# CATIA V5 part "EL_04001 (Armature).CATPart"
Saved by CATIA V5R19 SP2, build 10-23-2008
Part number: Armature
Bounding box of the stored display mesh (mm): x 0 to 331.074, y 0 to 115, z 0 to 2
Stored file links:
  C:\Users\loics\Documents\Centrale Lyon\EPSA\GIT\ELIZ-2021\EL_Electrical\CATIA\EL_A0100 (Dash Panel)\EL_04001 (Armature).CATPart
  C:\Users\loics\Documents\Centrale Lyon\EPSA\GIT\ELIZ-2021\EL_Electrical\CATIA\EL_A0100 (Dash Panel)\EL_04004 (Bistable Switch).CATPart
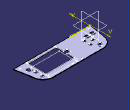
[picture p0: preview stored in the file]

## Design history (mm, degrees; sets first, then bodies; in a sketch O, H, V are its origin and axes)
Body1 (main body)
  Sketch1 on xy-plane, origin (0, 0, 0), H (1, 0, 0), V (0, 1, 0)
    line L1 (58.0371, 115) -> (273.0371, 115)
    line L2 (317.3534, 77.8142) -> (331.0742, 0)
    line L3 (331.0742, 0) -> (0, 0)
    point P2 (0, 0)
    line L4 (0, 0) -> (13.7207, 77.8142)
    arc A1 centre (58.0371, 70) radius 45 from (13.7207, 77.8142) to (58.0371, 115) cw
    point P4 (58.0371, 115)
    arc A2 centre (273.0371, 70) radius 45 from (273.0371, 115) to (317.3534, 77.8142) cw
    point P6 (273.0371, 115)
    distance H L3 = 0
    angle L4 L3 = 80
    angle L3 L2 = 80
    radius A1 = 45
    radius A2 = 45
    distance P4 P6 = 215
    distance L3 L1 = 115
    distance V P2 = 0
    horizontal: L1 H, L3 H
    tangency: A1 L4, A1 L1, A2 L1, A2 L2
  Pad1: profile Sketch1, direction (0, 0, 1), length 2
  Sketch2 on end face of Pad1, origin (0, 0, 2), H (1, 0, 0), V (0, 1, 0)
    construction line L1 (157.2489, 99) -> (157.2489, 5)
    construction line L2 (277.2489, 99) -> (277.2489, 5)
    circle A1 centre (157.2489, 99) radius 1.6
    circle A2 centre (157.2489, 5) radius 1.6
    circle A3 centre (277.2489, 5) radius 1.6
    circle A4 centre (277.2489, 99) radius 1.6
    construction line L3 (157.2489, 99) -> (277.2489, 99)
    construction line L4 (157.2489, 5) -> (277.2489, 5)
    circle A5 centre (300.8938, 36.6) radius 9.6
    point P5 (300.8938, 36.6)
    point P6 (163.611, 108)
    construction line L5 (142.011, 108) -> (182.011, 108)
    point P7 (142.011, 108)
    point P8 (182.011, 108)
    circle A6 centre (162.011, 108) radius 1.6
    point P9 (162.011, 108)
    circle A7 centre (182.011, 108) radius 2.5
    circle A8 centre (142.011, 108) radius 2.5
    reference projected line E2 (269.5105, 115) -> (54.5105, 115) from edge [face of Pad1 from Sketch1.L1 | end face of Pad1]
    point P10 (133.81, 30)
    point P11 (185.31, 30)
    arc A9 centre (293.2489, 60) radius 6.35 from (293.8989, 53.6834) to (292.5989, 53.6834) ccw
    point P12 (293.2489, 60)
    construction line L6 (324.021, 0) -> (324.021, 124.6381)
    point P13 (324.021, 0)
    construction line L7 (300.8938, 36.6) -> (355.7124, 46.266)
    point P16 (293.2489, 86.5)
    arc A10 centre (293.2489, 86.5) radius 6.35 from (293.8989, 80.1834) to (292.5989, 80.1834) ccw
    construction line L8 (24.6, 36.6) -> (49.6, 36.6)
    point P17 (24.6, 36.6)
    point P18 (49.6, 36.6)
    circle A11 centre (49.6, 36.6) radius 9.6
    circle A12 centre (24.6, 36.6) radius 9.6
    arc A13 centre (49.6, 61.6) radius 6.35 from (50.25, 55.2834) to (48.95, 55.2834) ccw
    point P19 (49.6, 61.6)
    arc A14 centre (72.1167, 74.6) radius 6.35 from (72.7667, 68.2834) to (71.4667, 68.2834) ccw
    point P20 (72.1167, 74.6)
    arc A15 centre (72.1167, 48.6) radius 6.35 from (72.7667, 42.2834) to (71.4667, 42.2834) ccw
    point P21 (72.1167, 48.6)
    point P22 (83.0841, 46.1824)
    point P23 (105.3433, 34.8012)
    point P24 (102.1, 31.6)
    circle A16 centre (37.1, 49.5518) radius 2.5
    construction line L9 (324.021, 75.8985) -> (330.0441, 41.74)
    point P26 (324.021, 75.8985)
    point P27 (330.0441, 41.74)
    reference projected line E3 (330.8615, 1.2061) -> (320.6673, 59.0203) from edge [face of Pad1 from Sketch1.L2 | end face of Pad1]
    arc A17 centre (51, 94.515) radius 8.1 from (50.15, 102.5703) to (51.85, 102.5703) ccw
    point P28 (51, 94.515)
    line L10 (292.5989, 81.5) -> (293.8989, 81.5)
    line L11 (293.8989, 81.5) -> (293.8989, 80.1834)
    line L12 (292.5989, 81.5) -> (292.5989, 80.1834)
    construction line L13 (37.1, 49.5518) -> (24.6, 36.6)
    point P33 (24.6, 36.6)
    construction line L14 (37.1, 49.5518) -> (49.6, 36.6)
    point P34 (49.6, 36.6)
    line L15 (292.5989, 53.6834) -> (292.5989, 55)
    line L16 (292.5989, 55) -> (293.8989, 55)
    line L17 (293.8989, 55) -> (293.8989, 53.6834)
    line L18 (50.15, 102.5703) -> (50.15, 101.615)
    line L19 (50.15, 101.615) -> (51.85, 101.615)
    line L20 (51.85, 101.615) -> (51.85, 102.5703)
    line L21 (48.95, 55.2834) -> (48.95, 56.6)
    line L22 (48.95, 56.6) -> (50.25, 56.6)
    line L23 (50.25, 56.6) -> (50.25, 55.2834)
    line L24 (71.4667, 68.2834) -> (71.4667, 69.6)
    line L25 (71.4667, 69.6) -> (72.7667, 69.6)
    line L26 (72.7667, 69.6) -> (72.7667, 68.2834)
    reference projected line E4 (269.5105, 115) -> (54.5105, 115) from edge [face of Pad1 from Sketch1.L1 | end face of Pad1]
    reference projected line E5 (269.5105, 115) -> (54.5105, 115) from edge [face of Pad1 from Sketch1.L1 | end face of Pad1]
    reference projected line E6 (269.5105, 115) -> (54.5105, 115) from edge [face of Pad1 from Sketch1.L1 | end face of Pad1]
    reference projected line E7 (0, 0) -> (331.0742, 0) from edge [face of Pad1 from Sketch1.L3 | end face of Pad1]
    line L27 (156.2489, 88.19) -> (278.2489, 88.19)
    line L28 (278.2489, 88.19) -> (278.2489, 10.492)
    line L29 (278.2489, 10.492) -> (156.2489, 10.492)
    construction line L30 (293.2489, 60) -> (293.2489, 86.5)
    reference projected line E8 (273.0371, 115) -> (58.0371, 115) from edge [face of Pad1 from Sketch1.L1 | end face of Pad1]
    circle A18 centre (313.7268, 12) radius 1.6
    point P57 (313.7268, 12)
    reference projected line E9 (0, 0) -> (331.0742, 0) from edge [face of Pad1 from Sketch1.L3 | end face of Pad1]
    reference projected line E10 (331.0742, 0) -> (317.3534, 77.8142) from edge [face of Pad1 from Sketch1.L2 | end face of Pad1]
    circle A19 centre (17.3473, 12) radius 1.6
    point P58 (17.3473, 12)
    reference projected line E11 (0, 0) -> (331.0742, 0) from edge [face of Pad1 from Sketch1.L3 | end face of Pad1]
    reference projected line E12 (13.7207, 77.8142) -> (0, 0) from edge [face of Pad1 from Sketch1.L4 | end face of Pad1]
    reference projected line E13 (331.0742, 0) -> (317.3534, 77.8142) from edge [face of Pad1 from Sketch1.L2 | end face of Pad1]
    line L31 (72.7667, 42.2834) -> (72.7667, 43.6)
    line L32 (71.4667, 43.6) -> (72.7667, 43.6)
    construction line L33 (72.1167, 74.6) -> (72.1167, 48.6)
    line L34 (71.4667, 43.6) -> (71.4667, 42.2834)
    axis line L35 (72.1167, 61.6) -> (49.6, 61.6)
    point P61 (72.1167, 61.6)
    line L36 (156.2489, 88.19) -> (156.2489, 57.0885)
    line L37 (156.2489, 57.0885) -> (141.2489, 57.0885)
    line L38 (141.2489, 57.0885) -> (141.2489, 41.6307)
    line L39 (141.2489, 41.6307) -> (156.2489, 41.6307)
    point P65 (156.2489, 41.6307)
    line L40 (156.2489, 41.6307) -> (156.2489, 10.492)
    reference projected line E14 (156.2489, 57.0885) -> (154.2489, 57.0885) from edge of DatumCurve1
    reference projected line E15 (156.2489, 41.6307) -> (154.2489, 41.6307) from edge of DatumCurve2
    radius A1 = 1.6
    radius A2 = 1.6
    radius A3 = 1.6
    radius A4 = 1.6
    length L2 = 94
    radius A5 = 9.6
    radius A8 = 2.5
    radius A7 = 2.5
    radius A6 = 1.6
    distance P7 P9 = 20
    distance P9 P8 = 20
    distance P9 V = 162.011
    distance L5 E2 = 7
    distance P10 V = 133.81
    radius A9 = 6.35
    distance L6 V = 324.021
    radius A10 = 6.35
    radius A12 = 9.6
    radius A11 = 9.6
    length L8 = 25
    distance P17 V = 24.6
    radius A13 = 6.35
    distance P19 P18 = 25
    distance P19 V = 49.6
    radius A14 = 6.35
    radius A15 = 6.35
    radius A16 = 2.5
    distance L9 A5 = 20
    radius A17 = 8.1
    distance P28 V = 51
    length L10 = 1.3
    distance P16 L12 = 0.65
    distance L10 P16 = 5
    distance P20 P19 = 26
    length L13 = 18
    length L14 = 18
    length L16 = 1.3
    distance L17 P12 = 0.65
    length L19 = 1.7
    distance L20 P28 = 0.85
    distance L19 P28 = 7.1
    length L22 = 1.3
    distance L21 P19 = 0.65
    length L25 = 1.3
    distance L26 P20 = 0.65
    distance L25 P20 = 5
    distance L22 P19 = 5
    distance P12 L16 = 5
    distance P28 E4 = 20.485
    distance P34 E5 = 78.4
    distance P5 E6 = 78.4
    length L3 = 120
    distance L4 E7 = 5
    distance L2 P16 = 16
    length L28 = 77.698
    length L27 = 122
    distance L4 L29 = 5.492
    distance L28 L2 = 1
    distance P5 L30 = 7.6449
    distance P16 E8 = 28.5
    length L30 = 26.5
    radius A18 = 1.6
    distance P57 E9 = 12
    distance P57 E10 = 15
    radius A19 = 1.6
    distance P58 E11 = 12
    distance E12 P58 = 15
    distance P12 E13 = 26.8317
    distance P21 L32 = 5
    length L32 = 1.3
    distance P21 L31 = 0.65
    length L33 = 26
    distance L35 P21 = 13
    length L37 = 15
    vertical: L1 V, L2 V, L6 V, L11 V, L12 V, L15 V, L17 V, L18 V, L20 V, L21 V, L23 V, L24 V, L26 V, L28 V, L30 V, L31 V, L33 V, L34 V, L36 V, L40 V, L38 V
    horizontal: L3 H, L4 H, L5 H, L8 H, L10 H, L16 H, L19 H, L22 H, L25 H, L27 H, L29 H, L32 H, L35 H, L37 H, L39 H
    coincidence: P9 L5, A6 P6, P13 H, P26 L6, P27 L7, L13 P17, L14 P18, P33 P17, P34 P18, P61 L33, P65 L36, L37 E14, L39 E15
    perpendicularity: L9 L7
    parallelism: L9 E3
  Pocket1: profile Sketch2, direction (0, 0, -1), length 2
  Sketch3 on start face of Pad1, origin (0, 0, 0), H (1, 0, 0), V (0, -1, 0)
    line L1 (162.4989, -29.4) -> (282.4989, -29.4)
    line L2 (282.4989, -29.4) -> (282.4989, -103.4)
    line L3 (282.4989, -103.4) -> (162.4989, -103.4)
    line L4 (162.4989, -103.4) -> (162.4989, -29.4)
    reference projected line E1 (175.7489, -32.8) -> (281.2489, -32.8) from edge of Sketch2
    reference projected line E2 (169.7489, -80) -> (169.7489, -12.8) from edge of Sketch2
    length L1 = 120
    distance E1 L1 = 3.4
    length L4 = 74
    distance L4 E2 = 7.25
    horizontal: L1 H, L3 H
    vertical: L2 V, L4 V
  Sketch4 on end face of Pad1, origin (0, 0, 2), H (1, 0, 0), V (0, 1, 0)
    line L1 (58.0371, 115) -> (273.0371, 115)
    line L2 (317.3534, 77.8142) -> (331.0742, 0)
    line L3 (331.0742, 0) -> (0, 0)
    point P2 (0, 0)
    line L4 (0, 0) -> (13.7207, 77.8142)
    arc A1 centre (58.0371, 70) radius 45 from (13.7207, 77.8142) to (58.0371, 115) cw
    point P4 (58.0371, 115)
    arc A2 centre (273.0371, 70) radius 45 from (273.0371, 115) to (317.3534, 77.8142) cw
    point P6 (273.0371, 115)
    distance H L3 = 0
    angle L4 L3 = 80
    angle L3 L2 = 80
    radius A1 = 45
    radius A2 = 45
    distance P4 P6 = 215
    distance L3 L1 = 115
    distance V P2 = 0
    horizontal: L1 H, L3 H
    tangency: A1 L4, A1 L1, A2 L1, A2 L2
  Pad2: profile Sketch4, direction (0, 0, 1), length 2
  Sketch5 on end face of Pad1, origin (0, 0, 0), H (1, 0, 0), V (0, 1, 0)
    line L1 (58.0371, 115) -> (273.0371, 115)
    line L2 (317.3534, 77.8142) -> (331.0742, 0)
    line L3 (331.0742, 0) -> (0, 0)
    point P2 (0, 0)
    line L4 (0, 0) -> (13.7207, 77.8142)
    arc A1 centre (58.0371, 70) radius 45 from (13.7207, 77.8142) to (58.0371, 115) cw
    point P4 (58.0371, 115)
    arc A2 centre (273.0371, 70) radius 45 from (273.0371, 115) to (317.3534, 77.8142) cw
    point P6 (273.0371, 115)
    distance H L3 = 0
    angle L4 L3 = 80
    angle L3 L2 = 80
    radius A1 = 45
    radius A2 = 45
    distance P4 P6 = 215
    distance L3 L1 = 115
    distance V P2 = 0
    horizontal: L1 H, L3 H
    tangency: A1 L4, A1 L1, A2 L1, A2 L2
  Pad3: profile Sketch5, direction (0, 0, 1), length 2
  DatumCurve1
  DatumCurve2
